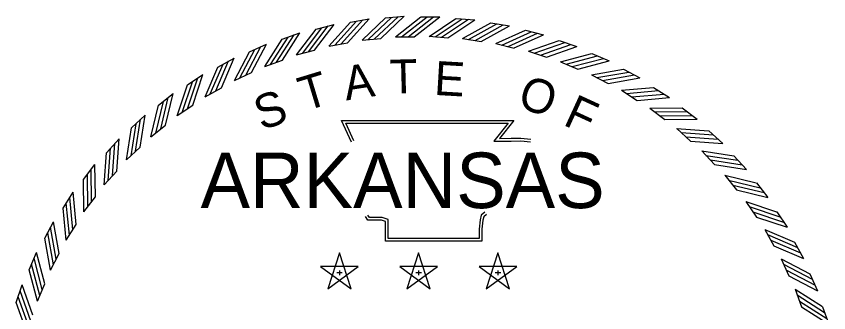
# Model space of a CAD drawing. Extents: x 166 to 3995, y -61 to 2074.
# Drawn here: x 2685.4 to 2921.9, y 574.8 to 661.1 of the extents above; entities that cross this region are included whole.
import ezdxf

# ---------------------------------------------------------------- set-up
doc = ezdxf.new("R2010")
doc.units = 0
doc.layers.add('STAMP_Byron', color=7, linetype='Continuous')

msp = doc.modelspace()

# ---------------------------------------------------------------- linework, layer by layer
at = {"layer": 'STAMP_Byron'}
for p, q in [((2782.75, 659.36), (2788.11, 660.3)), ((2782.75, 659.36), (2788.11, 660.3)), ((2792.94, 660.57), (2798.35, 661.07)), ((2792.94, 660.57), (2798.35, 661.07)), ((2803.24, 660.88), (2808.68, 660.88)), ((2803.24, 660.88), (2808.68, 660.88)), ((2813.43, 660.47), (2818.86, 660.07)), ((2813.43, 660.47), (2818.86, 660.07)), ((2772.7, 657.3), (2777.97, 658.69)), ((2772.7, 657.3), (2777.97, 658.69)), ((2823.6, 659.15), (2828.98, 658.3)), ((2823.6, 659.15), (2828.98, 658.3)), ((2762.86, 654.43), (2767.99, 656.24)), ((2762.86, 654.43), (2767.99, 656.24)), ((2805.6, 655.24), (2811.04, 654.84)), ((2805.6, 655.24), (2811.04, 654.84)), ((2833.63, 656.99), (2838.91, 655.71)), ((2833.63, 656.99), (2838.91, 655.71)), ((2753.29, 650.75), (2758.25, 652.98)), ((2753.29, 650.75), (2758.25, 652.98)), ((2776.45, 652.37), (2781.82, 653.31)), ((2776.45, 652.37), (2781.82, 653.31)), ((2786.07, 654.13), (2791.5, 654.63)), ((2786.07, 654.13), (2791.5, 654.63)), ((2795.81, 655.09), (2801.27, 655.09)), ((2795.81, 655.09), (2801.27, 655.09)), ((2815.37, 654.58), (2820.75, 653.74)), ((2815.37, 654.58), (2820.75, 653.74)), ((2825.04, 653.12), (2830.34, 651.83)), ((2825.04, 653.12), (2830.34, 651.83)), ((2843.44, 654.02), (2848.6, 652.3)), ((2843.44, 654.02), (2848.6, 652.3)), ((2767, 649.82), (2772.27, 651.2)), ((2767, 649.82), (2772.27, 651.2)), ((2834.57, 650.87), (2839.74, 649.15)), ((2834.57, 650.87), (2839.74, 649.15)), ((2744.05, 646.29), (2748.81, 648.92)), ((2744.05, 646.29), (2748.81, 648.92)), ((2757.79, 646.49), (2762.93, 648.31)), ((2757.79, 646.49), (2762.93, 648.31)), ((2852.98, 650.24), (2857.98, 648.1)), ((2852.98, 650.24), (2857.98, 648.1)), ((2843.87, 647.84), (2848.89, 645.69)), ((2843.87, 647.84), (2848.89, 645.69)), ((2735.21, 641.09), (2739.74, 644.1)), ((2735.21, 641.09), (2739.74, 644.1)), ((2748.89, 642.42), (2753.86, 644.66)), ((2748.89, 642.42), (2753.86, 644.66)), ((2852.9, 644.04), (2857.72, 641.49)), ((2852.9, 644.04), (2857.72, 641.49)), ((2862.17, 645.69), (2866.98, 643.14)), ((2862.17, 645.69), (2866.98, 643.14)), ((2740.36, 637.63), (2745.13, 640.27)), ((2740.36, 637.63), (2745.13, 640.27)), ((2861.58, 639.52), (2866.17, 636.58)), ((2861.58, 639.52), (2866.17, 636.58)), ((2870.95, 640.39), (2875.53, 637.46)), ((2870.95, 640.39), (2875.53, 637.46)), ((2726.84, 635.17), (2731.1, 638.55)), ((2726.84, 635.17), (2731.1, 638.55)), ((2732.25, 632.15), (2736.78, 635.17)), ((2732.25, 632.15), (2736.78, 635.17)), ((2869.85, 634.3), (2874.19, 630.99)), ((2869.85, 634.3), (2874.19, 630.99)), ((2879.27, 634.39), (2883.59, 631.09)), ((2879.27, 634.39), (2883.59, 631.09)), ((2718.98, 628.58), (2722.95, 632.3)), ((2718.98, 628.58), (2722.95, 632.3)), ((2724.62, 626.02), (2728.89, 629.41)), ((2724.62, 626.02), (2728.89, 629.41)), ((2877.67, 628.41), (2881.72, 624.75)), ((2877.67, 628.41), (2881.72, 624.75)), ((2887.06, 627.72), (2891.1, 624.07)), ((2887.06, 627.72), (2891.1, 624.07)), ((2711.69, 621.37), (2715.34, 625.4)), ((2711.69, 621.37), (2715.34, 625.4)), ((2717.52, 619.28), (2721.5, 623.01)), ((2717.52, 619.28), (2721.5, 623.01)), ((2884.97, 621.89), (2888.7, 617.91)), ((2884.97, 621.89), (2888.7, 617.91)), ((2894.28, 620.43), (2898, 616.46)), ((2894.28, 620.43), (2898, 616.46)), ((2705.02, 613.57), (2708.32, 617.9)), ((2705.02, 613.57), (2708.32, 617.9)), ((2711, 611.97), (2714.66, 616.02)), ((2711, 611.97), (2714.66, 616.02)), ((2891.71, 614.79), (2895.1, 610.52)), ((2891.71, 614.79), (2895.1, 610.52)), ((2900.86, 612.57), (2904.24, 608.31)), ((2900.86, 612.57), (2904.24, 608.31)), ((2699.02, 605.26), (2701.95, 609.84)), ((2699.02, 605.26), (2701.95, 609.84)), ((2705.11, 604.16), (2708.42, 608.49)), ((2705.11, 604.16), (2708.42, 608.49)), ((2897.84, 607.16), (2900.87, 602.63)), ((2897.84, 607.16), (2900.87, 602.63)), ((2906.78, 604.2), (2909.8, 599.67)), ((2906.78, 604.2), (2909.8, 599.67)), ((2693.72, 596.47), (2696.27, 601.28)), ((2693.72, 596.47), (2696.27, 601.28)), ((2699.89, 595.88), (2702.83, 600.47)), ((2699.89, 595.88), (2702.83, 600.47)), ((2903.33, 599.05), (2905.96, 594.28)), ((2903.33, 599.05), (2905.96, 594.28)), ((2911.99, 595.36), (2914.62, 590.6)), ((2911.99, 595.36), (2914.62, 590.6)), ((2689.17, 587.28), (2691.31, 592.28)), ((2689.17, 587.28), (2691.31, 592.28)), ((2695.37, 587.2), (2697.92, 592.02)), ((2695.37, 587.2), (2697.92, 592.02)), ((2779.46, 592.23), (2776.06, 581.79)), ((2779.46, 592.23), (2776.06, 581.79)), ((2782.86, 581.79), (2779.47, 592.24)), ((2782.86, 581.79), (2779.47, 592.24)), ((2802.54, 592.23), (2799.14, 581.79)), ((2802.54, 592.23), (2799.14, 581.79)), ((2805.93, 581.79), (2802.55, 592.24)), ((2805.93, 581.79), (2802.55, 592.24)), ((2825.62, 592.23), (2822.22, 581.79)), ((2825.62, 592.23), (2822.22, 581.79)), ((2829.01, 581.79), (2825.63, 592.24)), ((2829.01, 581.79), (2825.63, 592.24)), ((2908.12, 590.52), (2910.35, 585.55)), ((2908.12, 590.52), (2910.35, 585.55)), ((2784.95, 588.24), (2773.97, 588.25)), ((2784.95, 588.24), (2773.97, 588.25)), ((2773.98, 588.24), (2782.86, 581.78)), ((2773.98, 588.24), (2782.86, 581.78)), ((2776.07, 581.79), (2784.96, 588.24)), ((2776.07, 581.79), (2784.96, 588.24)), ((2779.47, 587.07), (2779.47, 585.7)), ((2779.47, 587.07), (2779.47, 585.7)), ((2808.03, 588.24), (2797.05, 588.25)), ((2808.03, 588.24), (2797.05, 588.25)), ((2797.05, 588.24), (2805.93, 581.78)), ((2797.05, 588.24), (2805.93, 581.78)), ((2799.15, 581.79), (2808.04, 588.24)), ((2799.15, 581.79), (2808.04, 588.24)), ((2802.55, 587.07), (2802.55, 585.7)), ((2802.55, 587.07), (2802.55, 585.7)), ((2831.11, 588.24), (2820.12, 588.25)), ((2831.11, 588.24), (2820.12, 588.25)), ((2820.13, 588.24), (2829.01, 581.78)), ((2820.13, 588.24), (2829.01, 581.78)), ((2822.23, 581.79), (2831.12, 588.24)), ((2822.23, 581.79), (2831.12, 588.24)), ((2825.63, 587.07), (2825.63, 585.7)), ((2825.63, 587.07), (2825.63, 585.7)), ((2778.68, 586.49), (2780.31, 586.49)), ((2778.68, 586.49), (2780.31, 586.49)), ((2801.76, 586.49), (2803.39, 586.49)), ((2801.76, 586.49), (2803.39, 586.49)), ((2824.84, 586.49), (2826.47, 586.49)), ((2824.84, 586.49), (2826.47, 586.49)), ((2916.44, 586.12), (2918.67, 581.16)), ((2916.44, 586.12), (2918.67, 581.16)), ((2685.39, 577.75), (2687.11, 582.91)), ((2685.39, 577.75), (2687.11, 582.91)), ((2691.57, 578.18), (2693.72, 583.19)), ((2691.57, 578.18), (2693.72, 583.19)), ((2912.19, 581.62), (2914.01, 576.48)), ((2912.19, 581.62), (2914.01, 576.48)), ((2920.12, 576.55), (2921.94, 571.42)), ((2920.12, 576.55), (2921.94, 571.42))]:
    msp.add_line(p, q, dxfattribs=at)
for points in [[(2780.02, 653.02), (2786.33, 660.01)], [(2780.02, 653.02), (2786.33, 660.01)], [(2781.81, 653.32), (2788.12, 660.31)], [(2781.81, 653.32), (2788.12, 660.31)], [(2786.07, 654.12), (2792.93, 660.57)], [(2786.07, 654.12), (2792.93, 660.57)], [(2787.81, 654.27), (2794.67, 660.71)], [(2787.81, 654.27), (2794.67, 660.71)], [(2789.69, 654.48), (2796.55, 660.93)], [(2789.69, 654.48), (2796.55, 660.93)], [(2791.5, 654.63), (2798.36, 661.08)], [(2791.5, 654.63), (2798.36, 661.08)], [(2795.81, 655.08), (2803.23, 660.87)], [(2795.81, 655.08), (2803.23, 660.87)], [(2797.56, 655.07), (2804.98, 660.86)], [(2797.56, 655.07), (2804.98, 660.86)], [(2799.45, 655.11), (2806.87, 660.9)], [(2799.45, 655.11), (2806.87, 660.9)], [(2801.26, 655.09), (2808.68, 660.88)], [(2801.26, 655.09), (2808.68, 660.88)], [(2805.59, 655.23), (2813.42, 660.46)], [(2805.59, 655.23), (2813.42, 660.46)], [(2807.34, 655.09), (2815.17, 660.32)], [(2807.34, 655.09), (2815.17, 660.32)], [(2809.23, 654.99), (2817.06, 660.22)], [(2809.23, 654.99), (2817.06, 660.22)], [(2811.03, 654.84), (2818.86, 660.07)], [(2811.03, 654.84), (2818.86, 660.07)], [(2768.69, 650.24), (2774.4, 657.73)], [(2768.69, 650.24), (2774.4, 657.73)], [(2770.51, 650.76), (2776.21, 658.25)], [(2770.51, 650.76), (2776.21, 658.25)], [(2772.26, 651.2), (2777.97, 658.69)], [(2772.26, 651.2), (2777.97, 658.69)], [(2776.44, 652.36), (2782.75, 659.35)], [(2776.44, 652.36), (2782.75, 659.35)], [(2778.17, 652.65), (2784.47, 659.64)], [(2778.17, 652.65), (2784.47, 659.64)], [(2815.36, 654.58), (2823.59, 659.14)], [(2815.36, 654.58), (2823.59, 659.14)], [(2817.09, 654.29), (2825.32, 658.86)], [(2817.09, 654.29), (2825.32, 658.86)], [(2818.96, 654.04), (2827.19, 658.6)], [(2818.96, 654.04), (2827.19, 658.6)], [(2820.75, 653.74), (2828.98, 658.3)], [(2820.75, 653.74), (2828.98, 658.3)], [(2761.21, 647.72), (2766.28, 655.66)], [(2761.21, 647.72), (2766.28, 655.66)], [(2762.92, 648.31), (2767.99, 656.25)], [(2762.92, 648.31), (2767.99, 656.25)], [(2766.99, 649.81), (2772.7, 657.3)], [(2766.99, 649.81), (2772.7, 657.3)], [(2825.04, 653.12), (2833.62, 656.99)], [(2825.04, 653.12), (2833.62, 656.99)], [(2826.73, 652.69), (2835.32, 656.56)], [(2826.73, 652.69), (2835.32, 656.56)], [(2828.58, 652.28), (2837.16, 656.15)], [(2828.58, 652.28), (2837.16, 656.15)], [(2830.34, 651.84), (2838.92, 655.71)], [(2830.34, 651.84), (2838.92, 655.71)], [(2753.86, 644.66), (2758.25, 652.98)], [(2753.86, 644.66), (2758.25, 652.98)], [(2757.79, 646.49), (2762.85, 654.42)], [(2757.79, 646.49), (2762.85, 654.42)], [(2759.44, 647.05), (2764.51, 654.99)], [(2759.44, 647.05), (2764.51, 654.99)], [(2834.56, 650.87), (2843.43, 654.01)], [(2834.56, 650.87), (2843.43, 654.01)], [(2836.22, 650.3), (2845.09, 653.44)], [(2836.22, 650.3), (2845.09, 653.44)], [(2838.02, 649.74), (2846.9, 652.89)], [(2838.02, 649.74), (2846.9, 652.89)], [(2748.89, 642.41), (2753.28, 650.74)], [(2748.89, 642.41), (2753.28, 650.74)], [(2750.49, 643.12), (2754.89, 651.44)], [(2750.49, 643.12), (2754.89, 651.44)], [(2752.2, 643.93), (2756.59, 652.26)], [(2752.2, 643.93), (2756.59, 652.26)], [(2839.74, 649.15), (2848.61, 652.3)], [(2839.74, 649.15), (2848.61, 652.3)], [(2745.12, 640.27), (2748.81, 648.93)], [(2745.12, 640.27), (2748.81, 648.93)], [(2843.87, 647.83), (2852.97, 650.24)], [(2843.87, 647.83), (2852.97, 650.24)], [(2845.47, 647.13), (2854.57, 649.53)], [(2845.47, 647.13), (2854.57, 649.53)], [(2847.22, 646.43), (2856.33, 648.83)], [(2847.22, 646.43), (2856.33, 648.83)], [(2740.35, 637.62), (2744.05, 646.28)], [(2740.35, 637.62), (2744.05, 646.28)], [(2741.89, 638.46), (2745.59, 647.12)], [(2741.89, 638.46), (2745.59, 647.12)], [(2743.53, 639.41), (2747.22, 648.07)], [(2743.53, 639.41), (2747.22, 648.07)], [(2848.88, 645.7), (2857.99, 648.1)], [(2848.88, 645.7), (2857.99, 648.1)], [(2736.78, 635.17), (2739.74, 644.11)], [(2736.78, 635.17), (2739.74, 644.11)], [(2852.89, 644.04), (2862.16, 645.69)], [(2852.89, 644.04), (2862.16, 645.69)], [(2854.43, 643.21), (2863.7, 644.85)], [(2854.43, 643.21), (2863.7, 644.85)], [(2856.12, 642.36), (2865.39, 644.01)], [(2856.12, 642.36), (2865.39, 644.01)], [(2732.24, 632.14), (2735.21, 641.08)], [(2732.24, 632.14), (2735.21, 641.08)], [(2733.71, 633.1), (2736.68, 642.03)], [(2733.71, 633.1), (2736.68, 642.03)], [(2735.26, 634.18), (2738.22, 643.12)], [(2735.26, 634.18), (2738.22, 643.12)], [(2857.71, 641.5), (2866.98, 643.14)], [(2857.71, 641.5), (2866.98, 643.14)], [(2861.57, 639.52), (2870.94, 640.39)], [(2861.57, 639.52), (2870.94, 640.39)], [(2863.03, 638.56), (2872.41, 639.43)], [(2863.03, 638.56), (2872.41, 639.43)], [(2727.45, 628.29), (2729.67, 637.44)], [(2727.45, 628.29), (2729.67, 637.44)], [(2728.88, 629.41), (2731.1, 638.56)], [(2728.88, 629.41), (2731.1, 638.56)], [(2864.65, 637.58), (2874.02, 638.45)], [(2864.65, 637.58), (2874.02, 638.45)], [(2866.17, 636.59), (2875.54, 637.46)], [(2866.17, 636.59), (2875.54, 637.46)], [(2724.62, 626.01), (2726.83, 635.16)], [(2724.62, 626.01), (2726.83, 635.16)], [(2726, 627.09), (2728.22, 636.24)], [(2726, 627.09), (2728.22, 636.24)], [(2869.85, 634.3), (2879.26, 634.39)], [(2869.85, 634.3), (2879.26, 634.39)], [(2721.49, 623.01), (2722.95, 632.31)], [(2721.49, 623.01), (2722.95, 632.31)], [(2871.23, 633.22), (2880.64, 633.32)], [(2871.23, 633.22), (2880.64, 633.32)], [(2872.75, 632.11), (2882.17, 632.2)], [(2872.75, 632.11), (2882.17, 632.2)], [(2718.81, 620.46), (2720.26, 629.76)], [(2718.81, 620.46), (2720.26, 629.76)], [(2720.16, 621.78), (2721.61, 631.08)], [(2720.16, 621.78), (2721.61, 631.08)], [(2782.97, 624.46), (2780.07, 630.74), (2830.25, 630.77), (2826.05, 625.5), (2829.46, 625.55), (2832.31, 625.59), (2835.16, 625.28)], [(2782.97, 624.46), (2780.07, 630.74), (2830.25, 630.77), (2826.05, 625.5), (2829.46, 625.55), (2832.31, 625.59), (2835.16, 625.28)], [(2783.69, 624.8), (2781.31, 629.95), (2828.6, 629.98), (2824.39, 624.69), (2829.47, 624.75), (2832.27, 624.79), (2835.07, 624.49)], [(2783.69, 624.8), (2781.31, 629.95), (2828.6, 629.98), (2824.39, 624.69), (2829.47, 624.75), (2832.27, 624.79), (2835.07, 624.49)], [(2874.18, 630.99), (2883.6, 631.09)], [(2874.18, 630.99), (2883.6, 631.09)], [(2717.52, 619.27), (2718.97, 628.57)], [(2717.52, 619.27), (2718.97, 628.57)], [(2877.66, 628.41), (2887.05, 627.72)], [(2877.66, 628.41), (2887.05, 627.72)], [(2878.95, 627.22), (2888.34, 626.54)], [(2878.95, 627.22), (2888.34, 626.54)], [(2714.65, 616.02), (2715.34, 625.41)], [(2714.65, 616.02), (2715.34, 625.41)], [(2880.38, 625.98), (2889.77, 625.3)], [(2880.38, 625.98), (2889.77, 625.3)], [(2881.71, 624.76), (2891.1, 624.07)], [(2881.71, 624.76), (2891.1, 624.07)], [(2712.19, 613.25), (2712.87, 622.64)], [(2712.19, 613.25), (2712.87, 622.64)], [(2713.43, 614.69), (2714.11, 624.07)], [(2713.43, 614.69), (2714.11, 624.07)], [(2711, 611.97), (2711.69, 621.36)], [(2711, 611.97), (2711.69, 621.36)], [(2884.97, 621.89), (2894.27, 620.44)], [(2884.97, 621.89), (2894.27, 620.44)], [(2886.15, 620.6), (2895.45, 619.15)], [(2886.15, 620.6), (2895.45, 619.15)], [(2708.42, 608.49), (2708.32, 617.9)], [(2708.42, 608.49), (2708.32, 617.9)], [(2887.47, 619.25), (2896.78, 617.8)], [(2887.47, 619.25), (2896.78, 617.8)], [(2888.7, 617.92), (2898, 616.46)], [(2888.7, 617.92), (2898, 616.46)], [(2707.3, 607.06), (2707.21, 616.47)], [(2707.3, 607.06), (2707.21, 616.47)], [(2705.11, 604.15), (2705.02, 613.56)], [(2705.11, 604.15), (2705.02, 613.56)], [(2706.19, 605.53), (2706.09, 614.95)], [(2706.19, 605.53), (2706.09, 614.95)], [(2891.71, 614.79), (2900.85, 612.58)], [(2891.71, 614.79), (2900.85, 612.58)], [(2892.78, 613.41), (2901.93, 611.19)], [(2892.78, 613.41), (2901.93, 611.19)], [(2893.99, 611.96), (2903.14, 609.74)], [(2893.99, 611.96), (2903.14, 609.74)], [(2895.1, 610.53), (2904.25, 608.31)], [(2895.1, 610.53), (2904.25, 608.31)], [(2701.83, 598.95), (2700.96, 608.33)], [(2701.83, 598.95), (2700.96, 608.33)], [(2702.82, 600.47), (2701.95, 609.84)], [(2702.82, 600.47), (2701.95, 609.84)], [(2700.85, 597.34), (2699.97, 606.71)], [(2700.85, 597.34), (2699.97, 606.71)], [(2897.84, 607.17), (2906.77, 604.2)], [(2897.84, 607.17), (2906.77, 604.2)], [(2898.79, 605.7), (2907.73, 602.73)], [(2898.79, 605.7), (2907.73, 602.73)], [(2699.89, 595.87), (2699.02, 605.25)], [(2699.89, 595.87), (2699.02, 605.25)], [(2822.34, 603.43), (2821.48, 602.74), (2821.2, 601.7), (2820.92, 599.1), (2820.92, 595.63), (2792.91, 595.63), (2792.91, 600.31), (2792.91, 601.35), (2791.77, 601.7), (2787.78, 601.7), (2787.08, 602.78)], [(2822.34, 603.43), (2821.48, 602.74), (2821.2, 601.7), (2820.92, 599.1), (2820.92, 595.63), (2792.91, 595.63), (2792.91, 600.31), (2792.91, 601.35), (2791.77, 601.7), (2787.78, 601.7), (2787.08, 602.78)], [(2821.84, 604.05), (2820.78, 603.19), (2820.42, 601.85), (2820.12, 599.14), (2820.12, 596.42), (2793.7, 596.42), (2793.7, 600.31), (2793.7, 601.94), (2791.89, 602.49), (2788.21, 602.49), (2787.74, 603.21)], [(2821.84, 604.05), (2820.78, 603.19), (2820.42, 601.85), (2820.12, 599.14), (2820.12, 596.42), (2793.7, 596.42), (2793.7, 600.31), (2793.7, 601.94), (2791.89, 602.49), (2788.21, 602.49), (2787.74, 603.21)], [(2899.88, 604.15), (2908.81, 601.18)], [(2899.88, 604.15), (2908.81, 601.18)], [(2697.91, 592.02), (2696.27, 601.29)], [(2697.91, 592.02), (2696.27, 601.29)], [(2900.87, 602.63), (2909.8, 599.67)], [(2900.87, 602.63), (2909.8, 599.67)], [(2697.05, 590.42), (2695.4, 599.69)], [(2697.05, 590.42), (2695.4, 599.69)], [(2903.32, 599.06), (2911.98, 595.36)], [(2903.32, 599.06), (2911.98, 595.36)], [(2695.37, 587.19), (2693.72, 596.46)], [(2695.37, 587.19), (2693.72, 596.46)], [(2696.2, 588.73), (2694.56, 598)], [(2696.2, 588.73), (2694.56, 598)], [(2904.15, 597.52), (2912.81, 593.82)], [(2904.15, 597.52), (2912.81, 593.82)], [(2905.1, 595.88), (2913.76, 592.19)], [(2905.1, 595.88), (2913.76, 592.19)], [(2905.97, 594.29), (2914.62, 590.6)], [(2905.97, 594.29), (2914.62, 590.6)], [(2693.71, 583.19), (2691.31, 592.29)], [(2693.71, 583.19), (2691.31, 592.29)], [(2692.98, 581.53), (2690.58, 590.63)], [(2692.98, 581.53), (2690.58, 590.63)], [(2908.11, 590.52), (2916.43, 586.13)], [(2908.11, 590.52), (2916.43, 586.13)], [(2691.58, 578.17), (2689.17, 587.27)], [(2691.58, 578.17), (2689.17, 587.27)], [(2692.28, 579.77), (2689.88, 588.88)], [(2692.28, 579.77), (2689.88, 588.88)], [(2908.81, 588.92), (2917.14, 584.52)], [(2908.81, 588.92), (2917.14, 584.52)], [(2909.63, 587.21), (2917.95, 582.82)], [(2909.63, 587.21), (2917.95, 582.82)], [(2910.35, 585.55), (2918.68, 581.16)], [(2910.35, 585.55), (2918.68, 581.16)], [(2690.26, 574.04), (2687.11, 582.92)], [(2690.26, 574.04), (2687.11, 582.92)], [(2689.67, 572.33), (2686.52, 581.2)], [(2689.67, 572.33), (2686.52, 581.2)], [(2912.18, 581.62), (2920.11, 576.56)], [(2912.18, 581.62), (2920.11, 576.56)], [(2912.75, 579.97), (2920.68, 574.9)], [(2912.75, 579.97), (2920.68, 574.9)], [(2688.54, 568.87), (2685.4, 577.74)], [(2688.54, 568.87), (2685.4, 577.74)], [(2689.11, 570.52), (2685.97, 579.39)], [(2689.11, 570.52), (2685.97, 579.39)], [(2913.42, 578.2), (2921.35, 573.13)], [(2913.42, 578.2), (2921.35, 573.13)], [(2914.01, 576.49), (2921.94, 571.42)], [(2914.01, 576.49), (2921.94, 571.42)]]:
    msp.add_lwpolyline(points, dxfattribs=at)

# ---------------------------------------------------------------- texts
for s, rotation, p in [('T', 1.4789, (2794.22, 638.51)), ('T', 1.4789, (2794.22, 638.51)), ('A', 8.6788, (2781.44, 636.54)), ('A', 8.6788, (2781.44, 636.54)), ('E', 356.672, (2806.89, 638.21)), ('E', 356.672, (2806.89, 638.21)), ('T', 16.9015, (2769.42, 633.4)), ('T', 16.9015, (2769.42, 633.4)), ('O', 341.2218, (2830.92, 634.82)), ('O', 341.2218, (2830.92, 634.82)), ('S', 19.7726, (2756.83, 627.75)), ('S', 19.7726, (2756.83, 627.75)), ('F', 335.3628, (2844.26, 629.6)), ('F', 335.3628, (2844.26, 629.6))]:
    msp.add_text(s, height=9.9, rotation=rotation, dxfattribs=at).set_placement(p)
msp.add_text('ARKANSAS', height=16.155, dxfattribs=at).set_placement((2739.05, 605.24))
msp.add_text('ARKANSAS', height=16.155, dxfattribs=at).set_placement((2739.05, 605.24))

doc.saveas('drawing.dxf')
